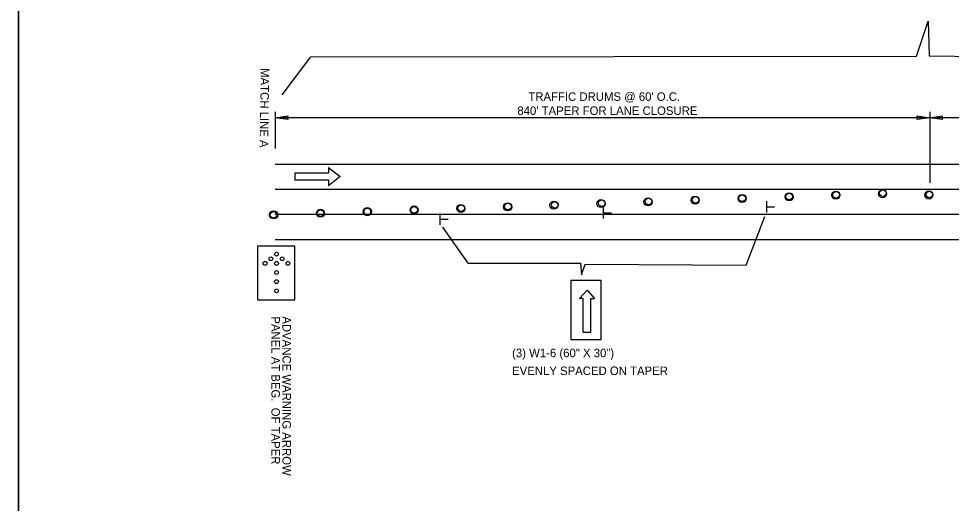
# Model space of a CAD drawing. Extents: x -100 to 745, y -1581 to -107.
# Drawn here: x 175.4 to 239.8, y -570 to -536.5 of the extents above; entities that cross this region are included whole.
import ezdxf

# ---------------------------------------------------------------- set-up
doc = ezdxf.new("R2010")
doc.units = 0
for name, color, linetype in [('Default', 7, 'Continuous'), ('R_Contour Annot', 7, 'Continuous'), ('R_Draft', 7, 'Continuous')]:
    doc.layers.add(name, color=color, linetype=linetype)

msp = doc.modelspace()

# ---------------------------------------------------------------- linework, layer by layer
at = {"layer": 'Default'}
for p, q in [((193.119, -542.97), (193.119, -545.497)), ((238.32, -542.97), (238.32, -545.719)), ((193.119, -543.384), (193.988, -543.253)), ((238.32, -543.384), (193.119, -543.384)), ((193.988, -543.514), (193.119, -543.384)), ((193.988, -543.253), (193.988, -543.514)), ((237.451, -543.514), (237.451, -543.253)), ((237.451, -543.253), (238.32, -543.384)), ((238.32, -543.384), (237.451, -543.514)), ((238.32, -543.237), (238.32, -547.872)), ((238.32, -543.384), (239.189, -543.253)), ((264.398, -543.384), (238.32, -543.384)), ((239.189, -543.514), (238.32, -543.384)), ((238.32, -543.618), (238.32, -547.275)), ((239.189, -543.253), (239.189, -543.514)), ((193.119, -546.581), (220.475, -546.581)), ((196.799, -546.818), (196.799, -547.213)), ((196.799, -546.818), (197.619, -547.45)), ((220.475, -546.581), (278.745, -546.581)), ((196.799, -547.213), (194.473, -547.213)), ((194.473, -547.213), (194.473, -547.687)), ((197.619, -547.45), (196.799, -548.083)), ((196.799, -547.687), (194.473, -547.687)), ((196.799, -547.687), (196.799, -548.083)), ((193.119, -548.32), (220.692, -548.32)), ((220.692, -548.32), (278.962, -548.32)), ((227.064, -549.927), (227.064, -549.145)), ((193.119, -550.058), (221.048, -550.058)), ((204.522, -550.78), (204.522, -549.998)), ((215.793, -550.354), (215.793, -549.572)), ((215.804, -549.965), (216.338, -549.965)), ((221.048, -550.058), (279.316, -550.058)), ((227.075, -549.538), (227.609, -549.538)), ((204.533, -550.391), (205.067, -550.391)), ((193.119, -551.797), (220.528, -551.797)), ((220.528, -551.797), (279.525, -551.797)), ((214.139, -555.871), (214.658, -555.302)), ((214.658, -555.302), (215.177, -555.871)), ((214.399, -555.871), (214.139, -555.871)), ((214.399, -558.201), (214.399, -555.871)), ((214.918, -558.201), (214.918, -555.871)), ((214.918, -555.871), (215.177, -555.871)), ((214.399, -558.201), (214.918, -558.201))]:
    msp.add_line(p, q, dxfattribs=at)
for points in [[(193.606, -541.797), (195.581, -539.179), (237.407, -539.131), (238.213, -536.712), (238.285, -539.096), (262.954, -539.43), (264.095, -542.027)], [(204.666, -550.944), (206.432, -553.425), (214.198, -553.425), (214.266, -554.243), (214.538, -553.493), (225.641, -553.561), (226.934, -550.214)]]:
    msp.add_lwpolyline(points, dxfattribs=at)
for points in [[(191.894, -552.256), (191.894, -555.98), (194.47, -555.98), (194.47, -552.256)], [(213.545, -554.636), (213.545, -558.722), (215.635, -558.722), (215.635, -554.636)]]:
    msp.add_lwpolyline(points, close=True, dxfattribs=at)
for centre, radius in [((225.371, -548.965), 0.281), ((225.38, -548.944), 0.229), ((228.621, -548.849), 0.281), ((228.617, -548.829), 0.229), ((231.842, -548.738), 0.281), ((231.853, -548.714), 0.229), ((235.067, -548.628), 0.281), ((235.09, -548.6), 0.229), ((238.265, -548.719), 0.281), ((238.288, -548.686), 0.229), ((238.3, -548.687), 0.229), ((205.948, -549.651), 0.281), ((205.959, -549.632), 0.229), ((209.181, -549.541), 0.281), ((209.196, -549.517), 0.229), ((212.37, -549.43), 0.281), ((212.433, -549.403), 0.229), ((215.62, -549.314), 0.281), ((215.669, -549.288), 0.229), ((218.87, -549.198), 0.281), ((218.906, -549.173), 0.229), ((222.12, -549.081), 0.281), ((222.143, -549.058), 0.229), ((193.014, -550.095), 0.281), ((193, -550.09), 0.229), ((193.012, -550.091), 0.229), ((196.247, -549.984), 0.281), ((196.249, -549.976), 0.229), ((199.481, -549.873), 0.281), ((199.486, -549.861), 0.229), ((202.714, -549.762), 0.281), ((202.722, -549.747), 0.229), ((192.817, -553.13), 0.131), ((193.211, -552.814), 0.131), ((193.606, -553.13), 0.131), ((192.422, -553.447), 0.131), ((193.211, -553.447), 0.131), ((194, -553.447), 0.131), ((193.211, -554.079), 0.131), ((193.211, -554.711), 0.131), ((193.211, -555.344), 0.131)]:
    msp.add_circle(centre, radius, dxfattribs=at)
at = {"layer": 'R_Contour Annot'}
msp.add_lwpolyline([(175.406, -480.582), (345.406, -480.582), (345.406, -590.582), (175.406, -590.582)], close=True, dxfattribs=at)
at = {"layer": 'R_Draft'}
msp.add_lwpolyline([(175.406, -480.582), (175.406, -590.582), (345.406, -590.582), (345.406, -480.582)], close=True, dxfattribs=at)

# ---------------------------------------------------------------- texts
at = {"layer": 'Default'}
for s, rotation, p in [('MATCH LINE A', 269.19408, (192.127, -539.951)), ('ADVANCE WARNING ARROW', 270, (193.626, -557.111)), ('PANEL AT BEG.  OF TAPER', 270, (192.861, -557.111)), ('(3) W1-6 (60" X 30")', 0.00754, (209.483, -559.933)), ('EVENLY SPACED ON TAPER', 0.00754, (209.483, -561.168))]:
    msp.add_text(s, height=0.5862, rotation=rotation, dxfattribs=at).set_placement(p)
for s, p in [("TRAFFIC DRUMS @ 60' O.C.", (210.603, -542.214)), ("840' TAPER FOR LANE CLOSURE", (209.847, -543.188))]:
    msp.add_text(s, height=0.5862, dxfattribs=at).set_placement(p)

doc.saveas('drawing.dxf')
